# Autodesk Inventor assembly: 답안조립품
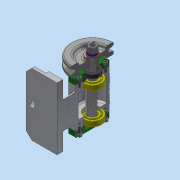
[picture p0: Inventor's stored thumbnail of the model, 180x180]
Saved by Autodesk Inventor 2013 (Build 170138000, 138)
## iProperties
Created: 2018-06
Part Number: 답안조립품
Document SubType Name: Assembly
Designer: Administrator
Author: Administrator
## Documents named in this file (16)
- C:\Users\Administrator\Desktop\480608V1006\답안조립품.iam
- C:\Users\Administrator\Desktop\480608V1006\V벨트풀리.ipt
- C:\Users\Administrator\Desktop\480608V1006\고무캡.ipt
- C:\Users\Administrator\Desktop\480608V1006\너트 M8.ipt
- 너트 M8.ipt
- C:\Users\Administrator\Desktop\480608V1006\뒤커버.ipt
- C:\Users\Administrator\Desktop\480608V1006\베어링 15x32x9.ipt
- C:\Users\Administrator\Desktop\480608V1006\본체.ipt
- C:\Users\Administrator\Desktop\480608V1006\볼트 M4x12.ipt
- C:\Users\Administrator\Desktop\480608V1006\스프링와셔 8.ipt
- C:\Users\Administrator\Desktop\480608V1006\앞커버.ipt
- C:\Users\Administrator\Desktop\480608V1006\오일 실 15 25 7.ipt
- C:\Users\Administrator\Desktop\480608V1006\와셔 8x17.ipt
- C:\Users\Administrator\Desktop\480608V1006\축.ipt
- C:\Users\Administrator\Desktop\480608V1006\키 3x3x12.ipt
- 키 3x3x12.ipt
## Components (2 placed, 2 different names)
1. V벨트풀리:1
2. 고무캡:1
